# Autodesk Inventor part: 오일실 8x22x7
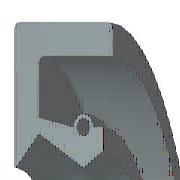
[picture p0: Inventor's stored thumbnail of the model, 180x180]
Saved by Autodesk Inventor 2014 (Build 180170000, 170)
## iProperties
IsCustomPart: 1
Created: 2009-02
Part Number: 오일실 8x22x7
Material: 고무
Description: 오일-실
Document SubType Name: Modeling
Standard: KS B 2804
Designer: 한국산업디자인학원
Standards Organization: KS
Language: ko-KR
Size Designation: D - 8 22 7
Categories: <MemberInstance><Categories><Category DisplayName="샤프트 부품" InternalName="7f7aeb1f-a693-4053-b835-cee3144e0d98" Mnemonic="SHFT"><Category DisplayName="실링" Intern
Density: 0.93 g/cm^3
Appearance: 고무 - 검은색 - 버전 1.1
Author: 한국산업디자인학원
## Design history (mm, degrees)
revolve "본체" stored, may be unused: angle "d17" = 90 deg
revolve "스프링1" stored, may be unused: angle "d18" = 90 deg
body "Solid1"
sketch "스케치1"
  geometry: L1 (0, 11)-(7, 11); L2 (7, 9.25)-(1.75, 9.25); L3 (1.75, 5.75)-(4.9, 4); L4 (4.9, 4)-(0, 4); L5 (0, 0)-(9.586, 0) reference; L6 (4.9, 4)-(6.3, 4.875); L7 (0, 18)-(0, -3) reference; L8 (-1.941, 0)-(11.507, 0) reference; L9 (4.2, 6.1)-(1.75, 6.59); L10 (1.75, 6.59)-(1.75, 9.25); L11 (0, 11)-(0, 4.088); L12 (4.9, 4)-(0, 4); L13 (1.75, 5.75)-(0.152, 4.028); L14 (7, 11)-(7, 9.25); L15 (5.6, 6.1)-(6.3, 6.1); L16 (6.3, 6.1)-(6.3, 4.875); C1 r 0.455 at (4.9, 6.1); A1 r 0.7 centre (4.9, 6.1) between (5.6, 6.1) and (4.2, 6.1); A2 r 0.088 centre (0.088, 4.088) between (0, 4.088) and (0.152, 4.028); 1 further point
  constraints: 28 end point, 5 horizontal alignment, 5 point on line, 4 point on circle, 4 vertical alignment, 3 centre point, 3 tangent, 2 collinear, 2 horizontal, 2 perpendicular, 1 coincident, 1 parallel
  dimensions: "d0" = 22 diameter of L1 L5 (= SD2); "d1" = 1.75 distance of L1.end L2.start (= SD); "d2" = 0.91 diameter of C1 (= SPDI); "d3" = 1.4 diameter of A1 (= SPDA); "d4" = 8 diameter of L3.end L5 (= NND); "d5" = 11.5 diameter of L3.start L5 (= TKDM); "d7" = 13.18 diameter of L9.end L5 (= TKDM + 0.24 x SWDT); "d8" = 1.75 distance between parallel lines of L11 L10 (= SD); "d9" = 4.9 distance from line of L11 C1.centre (= SPDST); "d10" = 12.2 diameter of C1.centre L5 (= HLDM); "d11" = 0.0875 radius of A2 (= 0.25 x LAB); "d12" = 6.3 distance between parallel lines of L11 L16 (= SDI); "d13" = 9.75 diameter of L6.end L5 (= ABDM); "d14" = 7 distance from line of L11 L1.end (= SWDT)
fillet "모깎기1" dims "d6" = 0.3 (= RR)
other parameters: "SD2" = 22 [user parameter; used in 1 equation term], "SWDT" = 7 [user parameter; used in 2 equation terms], "RR" = 0.3 [user parameter; used in 1 equation term], "SD" = 1.75 [user parameter; used in 2 equation terms], "NND" = 8 [user parameter; used in 1 equation term], "SPDA" = 1.4 [user parameter; used in 1 equation term], "SPDI" = 0.91 [user parameter; used in 1 equation term], "TKDM" = 11.5 [user parameter; used in 2 equation terms], "HLDM" = 12.2 [user parameter; used in 1 equation term], "ABDM" = 9.75 [user parameter; used in 1 equation term], "SDI" = 6.3 [user parameter; used in 1 equation term], "SPDST" = 4.9 [user parameter; used in 1 equation term], "LAB" = 0.35 [user parameter; used in 1 equation term], "d15" = 0, "d16" = 0, "d19" = 0
